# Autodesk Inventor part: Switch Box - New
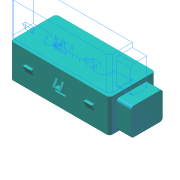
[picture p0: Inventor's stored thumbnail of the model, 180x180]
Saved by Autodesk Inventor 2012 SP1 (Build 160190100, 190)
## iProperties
Created: 2012-03
Part Number: Switch Box - New
Material: Default
Document SubType Name: Modeling
Designer: dmm70056
Density: 1 g/cm^3
Mass: 56.0607 g
Surface Area: 107.607 cm^2
Volume: 56.0607 cm^3
Author: dmm70056
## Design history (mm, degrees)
sketch "Sketch1"
  geometry: L1 (-34.3, 15.8)-(34.3, 15.8); L2 (34.3, 15.8)-(34.3, -15.8); L3 (34.3, -15.8)-(-34.3, -15.8); L4 (-34.3, -15.8)-(-34.3, 15.8); 1 further point
  constraints: 8 end point, 2 parallel, 1 horizontal, 1 perpendicular
  dimensions: "d0" = 68.6 distance of L2.end L3.end; "d1" = 34.3 distance from line of L4 point (0, 0) (= 0.5 x d0); "d2" = 31.6 distance of L3.end L1.start; "d3" = 15.8 distance from line of L3 point (0, 0) (= 0.5 x d2)
extrude "Extrusion1" new body sketch "Sketch1" distance "d4" = 23; taper "d5" = 0 deg
sketch "Sketch2"
  geometry: L1 (-21.75, 2.875)-(-21.75, -2.875); L2 (-12.25, -2.875)-(-12.25, 2.875); L3 (-2.25, 4.75)-(2.25, 4.75); L4 (2.25, -4.75)-(-2.25, -4.75); L5 (12.25, 2.875)-(12.25, -2.875); L6 (21.75, -2.875)-(21.75, 2.875); A1 r 4.75 centre (-17, -2.875) between (-21.75, -2.875) and (-12.25, -2.875); A2 r 4.75 centre (-17, 2.875) between (-12.25, 2.875) and (-21.75, 2.875); A3 r 4.75 centre (2.25, 0) between (2.25, -4.75) and (2.25, 4.75); A4 r 4.75 centre (-2.25, 0) between (-2.25, 4.75) and (-2.25, -4.75); A5 r 4.75 centre (17, -2.875) between (12.25, -2.875) and (21.75, -2.875); A6 r 4.75 centre (17, 2.875) between (21.75, 2.875) and (12.25, 2.875); 1 further point
  constraints: 12 end point, 12 point on circle, 12 tangent, 6 centre point, 3 horizontal alignment, 3 parallel, 2 perpendicular, 1 vertical
  dimensions: "d6" = 9.5 distance between parallel lines of L2 L1; "d7" = 9.5 distance between parallel lines of L3 L4; "d8" = 9.5 distance between parallel lines of L6 L5; "d9" = 5.75 distance of A6.centre A5.centre; "d10" = 2.875 vertical distance of point (0, 0) A5.centre (= 0.5 x d9); "d11" = 4.5 distance of A4.centre A3.centre; "d12" = 2.25 distance of A3.centre point (0, 0) (= 0.5 x d11); "d13" = 17 horizontal distance of point (0, 0) A2.centre; "d14" = 17 horizontal distance of point (0, 0) A6.centre
extrude "Extrusion2" join sketch "Sketch2" distance "d15" = 3.5; taper "d16" = -2 deg
sketch "Sketch3"
  geometry: C1 r 3 at (-17, 0); C2 r 3 at (0, 0); C3 r 3 at (17, 0); 1 further point
  constraints: 3 centre point, 2 equal radius, 2 horizontal alignment, 1 coincident
  dimensions: "d17" = 6 diameter of C2; "d18" = 17 distance of point (0, 0) C1.centre; "d19" = 17 distance of point (0, 0) C3.centre
extrude "Extrusion3" join sketch "Sketch3" distance "d20" = 12.75; taper "d21" = 0 deg
chamfer "Chamfer1" distance "d22" = 0.75; stored, may be unused: second distance "d23" = 2, angle "d24" = 45 deg
sketch "Sketch4"
  geometry: L1 (-15.8, 0)-(-15.8, 23) reference; L2 (-15.8, 0)-(-15.8, 23) reference; L3 (-15.8, 11.231)-(-18.8, 11.231); L4 (-18.8, 11.231)-(-15.8, 16.427); 1 further point
  constraints: 4 end point, 2 point on line, 1 perpendicular
  dimensions: "d25" = 3 distance of L3.start L3.end; "d26" = 60 deg angle of L3 L4
extrude "Extrusion4" join sketch "Sketch4" stored distance "d27" = 5.8; taper "d28" = 0 deg
sketch "Sketch5"
  geometry: L1 (32.9, 16.427)-(35.7, 16.427); L2 (35.7, 16.427)-(35.7, 12.731); L3 (35.7, 12.731)-(32.9, 12.731); L4 (32.9, 12.731)-(32.9, 16.427); L5 (31.4, 16.427)-(37.2, 16.427) reference; L6 (31.4, 16.427)-(31.4, 11.231) reference; L7 (31.4, 11.231)-(31.4, 16.427) reference; L8 (31.4, 11.231)-(37.2, 11.231) reference; L9 (37.2, 11.231)-(31.4, 11.231) reference; L10 (37.2, 16.427)-(37.2, 11.231) reference; L11 (37.2, 11.231)-(37.2, 16.427) reference; 1 further point
  constraints: 8 end point, 2 parallel, 1 collinear, 1 horizontal, 1 perpendicular
  dimensions: "d29" = 1.5 distance between parallel lines of L10 L2; "d30" = 1.5 distance between parallel lines of L6 L4; "d31" = 1.5 distance between parallel lines of L8 L3
extrude "Extrusion5" cut sketch "Sketch5" stored distance "d32" = 6; taper "d33" = 0 deg
fillet "Fillet1" dims "d34" = 0.75
fillet "Fillet2" dims "d35" = 0.75
sketch "Sketch6"
  geometry: L1 (31.4, 11.231)-(37.2, 11.231) reference; L2 (37.2, 11.231)-(31.4, 11.231) reference; L3 (30.4, 11.231)-(38.2, 11.231); L4 (38.2, 11.231)-(38.2, 8.231); L5 (38.2, 8.231)-(30.4, 8.231); L6 (30.4, 8.231)-(30.4, 11.231); L7 (31.4, 11.231)-(31.4, 16.427) reference; L8 (37.2, 16.427)-(37.2, 11.231) reference; L9 (37.2, 11.231)-(31.4, 11.231) reference; 1 further point
  constraints: 8 end point, 2 parallel, 1 collinear, 1 horizontal, 1 perpendicular
  dimensions: "d36" = 1 distance between parallel lines of L6 L7; "d37" = 1 distance between parallel lines of L8 L4; "d38" = 3 distance between parallel lines of L1 L5
extrude "Extrusion6" cut sketch "Sketch6" distance "d39" = 1; taper "d40" = 0 deg
fillet "Fillet3" dims "d41" = 0.75
workplane "Work Plane1"
sketch "Sketch7"
  geometry: L1 (-15.8, 0)-(-15.8, 23) reference; L2 (-15.8, 0)-(-15.8, 23) reference; L3 (-15.8, 10.481)-(-15.8, 11.231) reference; L4 (-15.8, 10.481)-(-15.8, 8.981) reference; L5 (-15.8, 8.231)-(-15.8, 8.981) reference; L6 (-15.8, 8.981)-(-15.8, 8.231) reference; L7 (-15.8, 8.981)-(-15.8, 10.481) reference; L8 (-15.8, 11.231)-(-15.8, 10.481) reference; L9 (-15.8, 11.231)-(-15.8, 16.427) reference; L10 (-15.8, 13.481)-(-15.8, 16.427) reference; L11 (-15.8, 13.481)-(-15.8, 12.731) reference; L12 (-15.8, 12.731)-(-15.8, 13.481) reference; L13 (-15.8, 16.427)-(-15.8, 13.481) reference; L14 (-15.8, 16.427)-(-15.8, 11.231) reference; L15 (-15.8, 14.031)-(-17.8, 14.031); L16 (15.8, 0)-(-15.8, 0) reference; L17 (-17.8, 14.031)-(-15.8, 9.742); L18 (-15.8, 11.231)-(-14.8, 11.231) reference; L19 (-15.8, 11.231)-(-17.501, 11.231) reference; L20 (-17.501, 11.231)-(-15.8, 11.231) reference; L21 (-14.8, 11.231)-(-15.8, 11.231) reference; 1 further point
  constraints: 4 end point, 2 point on line, 1 perpendicular
  dimensions: "d44" = 2 distance of L15.start L15.end; "d45" = 25 deg angle of L1 L17; "d62" = 2.8 distance between parallel lines of L19 L15
extrude "Extrusion7" join sketch "Sketch7" stored distance "d46" = 5.6; taper "d47" = 0 deg
mirror "Mirror1"
mirror "Mirror2"
fillet "Fillet7" dims "d61" = 2
sketch "Sketch10"
  geometry: L1 (-1, 2.8)-(-20, 2.8); L2 (-20, 2.8)-(-20, 24.8); L3 (-20, 24.8)-(-1, 24.8); L4 (-1, 24.8)-(-1, 2.8); 1 further point
  constraints: 8 end point, 2 parallel, 1 horizontal, 1 perpendicular
  dimensions: "d67" = 1 distance from line of L4 point (0, 13.8); "d68" = 19 distance of L2.end L3.end; "d69" = 22 distance of L3.end L1.start; "d70" = 11 distance from line of L3 point (0, 13.8) (= 0.5 x d69)
extrude "Extrusion10" join sketch "Sketch10" distance "d71" = 10; taper "d72" = 0 deg
fillet "Fillet9" dims "d73" = 2
body "Solid1"
node "Projected Loop1"
node "Projected Loop2"
node "Projected Loop3"
node "Projected Loop4"
node "Projected Loop5"
node "Projected Loop6"
node "Projected Loop10"
other parameters: "d42" = 21
